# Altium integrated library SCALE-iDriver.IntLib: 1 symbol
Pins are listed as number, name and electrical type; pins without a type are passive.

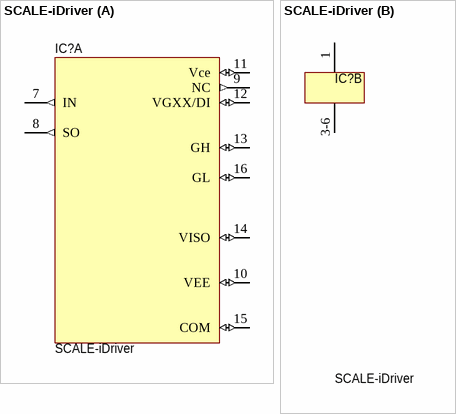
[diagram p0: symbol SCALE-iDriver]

## SCALE-iDriver
designator IC?
Part Number: SID11x2K; Manufacturer 1: Power Integrations; Second Source: N
footprint eSOP-R16B (SOIC, 16-Leads, Body 10.30x9.00mm, Pitch 1.27mm, IPC Medium Density)
part A pins: 7 IN (out), 8 SO (out), 9 NC (out), 10 VEE (io), 11 Vce (io), 12 VGXX/DI (io), 13 GH (io), 14 VISO (io), 15 COM (io), 16 GL (io)
part B pins: 1 VCC (power), 3-6 GND (power)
